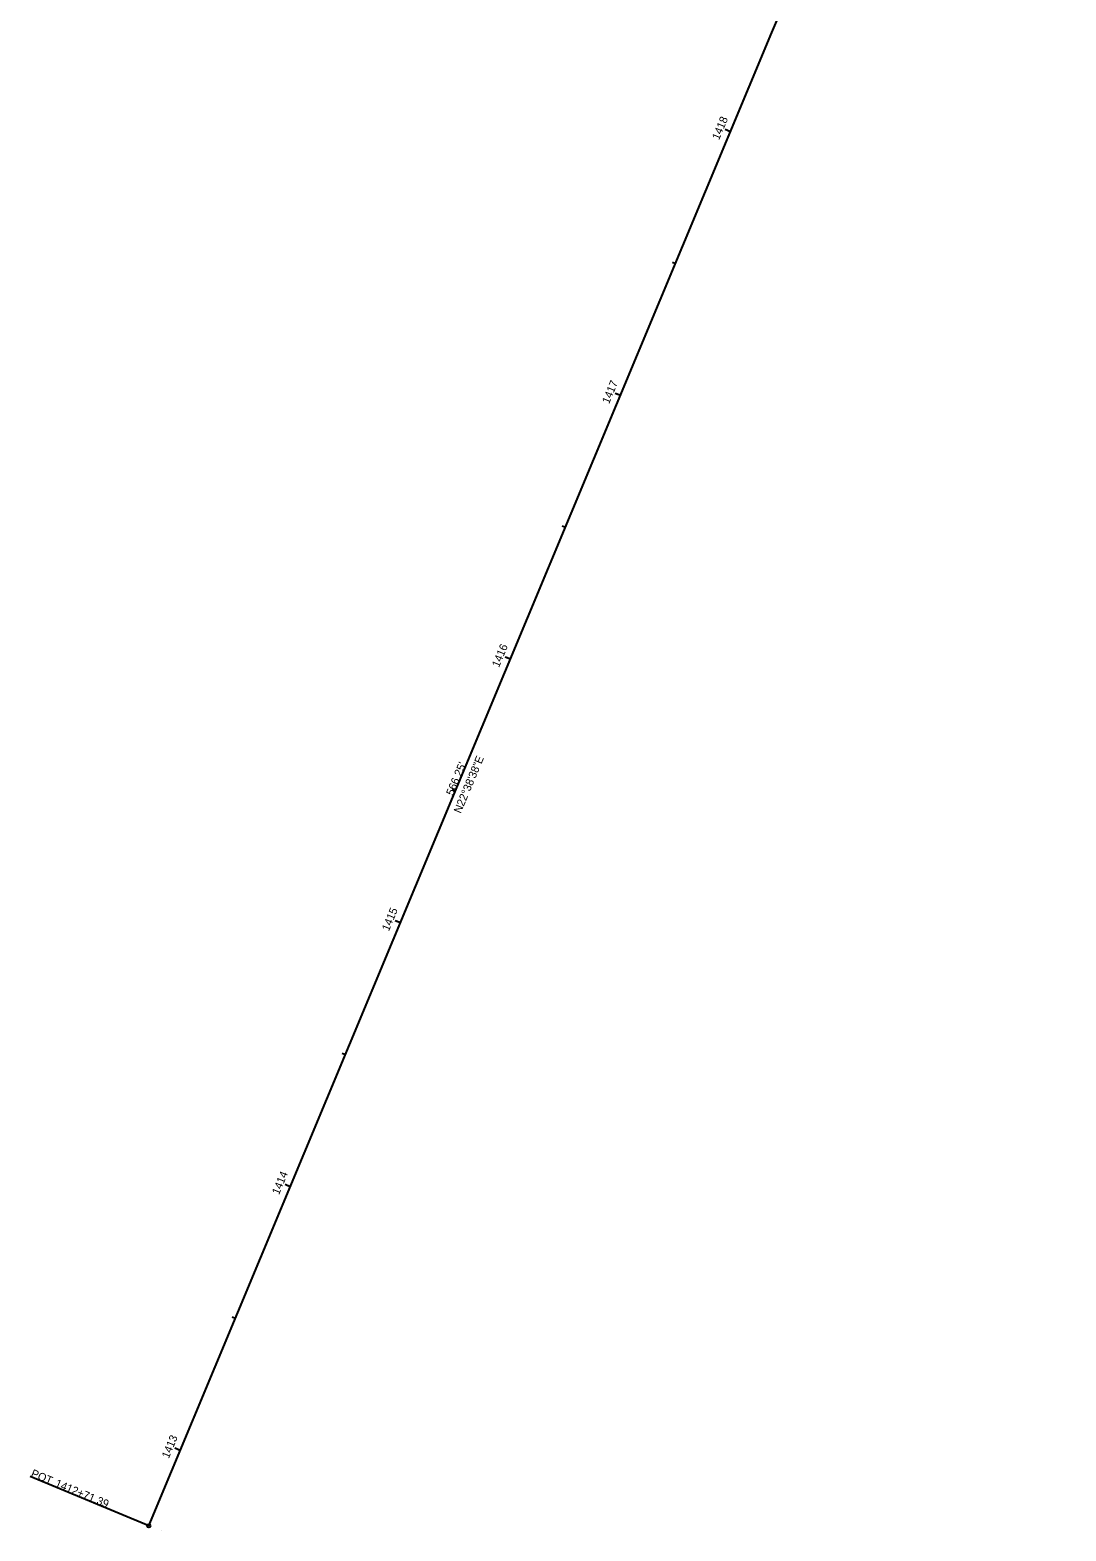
# Model space of a CAD drawing. Extents: x 158351 to 160372, y 373672 to 375743.
# Drawn here: x 158351 to 158713, y 373672 to 374197 of the extents above; entities that cross this region are included whole.
import ezdxf

# ---------------------------------------------------------------- set-up
doc = ezdxf.new("R2010")
doc.units = 0
for name, color, linetype in [('GE_X_Alignment', 7, 'Continuous'), ('GE_X_Alignment_1000_Bearings', 7, 'Continuous'), ('GE_X_Alignment_1000_Cardinal_Points', 7, 'Continuous'), ('GE_X_Alignment_1000_Distances', 7, 'Continuous'), ('GE_X_Alignment_1000_Stations', 7, 'Continuous'), ('GE_X_Alignment_100_Bearings', 7, 'Continuous'), ('GE_X_Alignment_100_Cardinal_Points', 7, 'Continuous'), ('GE_X_Alignment_100_Distances', 7, 'Continuous'), ('GE_X_Alignment_100_Stations', 7, 'Continuous'), ('GE_X_Alignment_500_Bearings', 7, 'Continuous'), ('GE_X_Alignment_500_Cardinal_Points', 7, 'Continuous'), ('GE_X_Alignment_500_Distances', 7, 'Continuous'), ('GE_X_Alignment_500_Stations', 7, 'Continuous')]:
    doc.layers.add(name, color=color, linetype=linetype)

msp = doc.modelspace()

# ---------------------------------------------------------------- linework, layer by layer
at = {"layer": 'GE_X_Alignment'}
for p, q in [((158392.16, 373673.9), (158610.16, 374196.5)), ((158396.45, 373672.1), (158396.45, 373672.1))]:
    msp.add_line(p, q, dxfattribs=at)
msp.add_lwpolyline([(158610.16, 374196.5), (158615.74, 374209.73), (158634.02, 374253.79), (158653.96, 374300.37), (158672.72, 374344.4), (158693.52, 374392.04), (158713.24, 374435.64), (158732.12, 374476.57), (158754.66, 374523.45), (158776.04, 374566.09), (158799.53, 374610.86), (158824.66, 374655.89), (158846.86, 374694.4), (158871.75, 374734.35), (158899.56, 374777.58), (158924.58, 374814.76), (158954.14, 374857.23), (158981.31, 374893.58), (159012.91, 374934.64), (159042.19, 374970.87), (159075.38, 375009.78)], dxfattribs=at)
at = {"layer": 'GE_X_Alignment_1000_Cardinal_Points'}
msp.add_line((158392.16, 373673.9), (158350.62, 373691.22), dxfattribs=at)
msp.add_circle((158392.16, 373673.9), 0.6, dxfattribs=at)
at = {"layer": 'GE_X_Alignment_1000_Stations'}
msp.add_line((158480.17, 373884.88), (158479.06, 373885.35), dxfattribs=at)
at = {"layer": 'GE_X_Alignment_100_Cardinal_Points'}
msp.add_line((158392.16, 373673.9), (158350.62, 373691.22), dxfattribs=at)
msp.add_circle((158392.16, 373673.9), 0.6, dxfattribs=at)
at = {"layer": 'GE_X_Alignment_100_Stations'}
for p, q in [((158595.67, 374161.76), (158593.83, 374162.53)), ((158576.42, 374115.61), (158575.31, 374116.08)), ((158557.17, 374069.47), (158555.33, 374070.24)), ((158537.92, 374023.32), (158536.81, 374023.78)), ((158518.67, 373977.18), (158516.83, 373977.95)), ((158499.42, 373931.03), (158498.31, 373931.49)), ((158480.17, 373884.88), (158478.33, 373885.65)), ((158460.92, 373838.74), (158459.81, 373839.2)), ((158441.67, 373792.59), (158439.83, 373793.36)), ((158422.42, 373746.45), (158421.31, 373746.91)), ((158403.17, 373700.3), (158401.32, 373701.07))]:
    msp.add_line(p, q, dxfattribs=at)
at = {"layer": 'GE_X_Alignment_500_Cardinal_Points'}
msp.add_line((158392.16, 373673.9), (158350.62, 373691.22), dxfattribs=at)
msp.add_circle((158392.16, 373673.9), 0.6, dxfattribs=at)
at = {"layer": 'GE_X_Alignment_500_Stations'}
for p, q in [((158595.67, 374161.76), (158594.56, 374162.22)), ((158557.17, 374069.47), (158556.06, 374069.93)), ((158518.67, 373977.18), (158517.56, 373977.64)), ((158480.17, 373884.88), (158478.33, 373885.65)), ((158441.67, 373792.59), (158440.56, 373793.06)), ((158403.17, 373700.3), (158402.06, 373700.76))]:
    msp.add_line(p, q, dxfattribs=at)

# ---------------------------------------------------------------- texts
at = {"layer": 'GE_X_Alignment_1000_Bearings'}
msp.add_text('N22°38\'38"E', height=2.8, rotation=67.3561, dxfattribs=at).set_placement((158501.28, 373923.03))
at = {"layer": 'GE_X_Alignment_1000_Cardinal_Points'}
for s, p in [('POT', (158350.7, 373691.24)), ('1412+71.39', (158359.12, 373687.73))]:
    msp.add_text(s, height=2.8, rotation=337.3561, dxfattribs=at).set_placement(p)
at = {"layer": 'GE_X_Alignment_1000_Distances'}
msp.add_text("566.25'", height=2.8, rotation=67.3561, dxfattribs=at).set_placement((158498.62, 373929.23))
at = {"layer": 'GE_X_Alignment_100_Bearings'}
msp.add_text('N22°38\'38"E', height=2.8, rotation=67.3561, dxfattribs=at).set_placement((158501.28, 373923.03))
at = {"layer": 'GE_X_Alignment_100_Cardinal_Points'}
for s, p in [('POT', (158350.7, 373691.24)), ('1412+71.39', (158359.12, 373687.73))]:
    msp.add_text(s, height=2.8, rotation=337.3561, dxfattribs=at).set_placement(p)
at = {"layer": 'GE_X_Alignment_100_Distances'}
msp.add_text("566.25'", height=2.8, rotation=67.3561, dxfattribs=at).set_placement((158498.62, 373929.23))
at = {"layer": 'GE_X_Alignment_100_Stations'}
for s, p in [('1418', (158591.64, 374158.71)), ('1417', (158553.16, 374066.35)), ('1416', (158514.64, 373974.12)), ('1415', (158476.13, 373881.82)), ('1414', (158437.7, 373789.56)), ('1413', (158399.14, 373697.27))]:
    msp.add_text(s, height=2.8, rotation=67.3561, dxfattribs=at).set_placement(p)
at = {"layer": 'GE_X_Alignment_500_Bearings'}
msp.add_text('N22°38\'38"E', height=2.8, rotation=67.3561, dxfattribs=at).set_placement((158501.28, 373923.03))
at = {"layer": 'GE_X_Alignment_500_Cardinal_Points'}
for s, p in [('POT', (158350.7, 373691.24)), ('1412+71.39', (158359.12, 373687.73))]:
    msp.add_text(s, height=2.8, rotation=337.3561, dxfattribs=at).set_placement(p)
at = {"layer": 'GE_X_Alignment_500_Distances'}
msp.add_text("566.25'", height=2.8, rotation=67.3561, dxfattribs=at).set_placement((158498.62, 373929.23))
at = {"layer": 'GE_X_Alignment_500_Stations'}
msp.add_text('1415', height=2.8, rotation=67.3561, dxfattribs=at).set_placement((158476.13, 373881.82))

doc.saveas('drawing.dxf')
